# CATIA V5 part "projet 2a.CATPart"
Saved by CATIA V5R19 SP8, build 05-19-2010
Part number: projet 2a
Bounding box of the stored display mesh (mm): x 0 to 50, y -25 to 25, z -25 to 25
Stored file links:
  C:\Documents and Settings\msamadi\Bureau\projet 2 vendredi\projet 2a.CATPart
  C:\Documents and Settings\msamadi\Bureau\Nouveau dossier\Product1.CATProduct
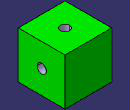
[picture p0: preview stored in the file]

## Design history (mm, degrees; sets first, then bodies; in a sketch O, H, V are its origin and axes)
Parameters
  LENGTH = 10 mm
Body1 (main body)
  Sketch1 on yz-plane, origin (0, 0, 0), H (0, 1, 0), V (0, 0, 1)
    line L1 (-25, 25) -> (25, 25)
    line L2 (25, 25) -> (25, -25)
    line L3 (25, -25) -> (-25, -25)
    line L4 (-25, -25) -> (-25, 25)
    length L1 = 50 {= LENGTH *5}
    length L2 = 50 {= LENGTH *5}
    distance L3 H = 25 {= LENGTH *2.5}
    distance L4 V = 25 {= LENGTH *2.5}
    horizontal: L1 H, L3 H
    vertical: L2 V, L4 V
  Pad1: profile Sketch1, direction (1, 0, 0), length 50 {= LENGTH *5}
  Sketch2 on end face of Pad1, origin (50, 0, 0), H (0, 1, 0), V (0, 0, 1)
    circle A1 centre (0, 0) radius 5
    distance O A1 = 5 {= LENGTH *0.5}
  Pocket1: profile Sketch2, direction (-1, 0, 0), through (limit type 6), offset 0 {= LENGTH *0}
  Sketch3 on face of Pad1 from Sketch1.L1, origin (0, 0, 25), H (1, 0, 0), V (0, 1, 0)
    circle A1 centre (25, 0) radius 5
    point P1 (25, 0)
    distance P1 V = 25 {= LENGTH *2.5}
    distance P1 A1 = 5 {= LENGTH *0.5}
    coincidence: P1 H
  Pocket2: profile Sketch3, direction (0, 0, -1), through (limit type 3), offset 0 {= LENGTH *0}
